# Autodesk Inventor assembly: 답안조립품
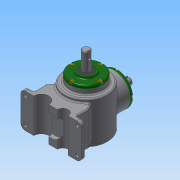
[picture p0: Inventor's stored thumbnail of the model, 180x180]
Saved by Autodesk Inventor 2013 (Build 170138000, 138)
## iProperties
Created: 2018-08
Part Number: 답안조립품
Document SubType Name: Assembly
Designer: user
Author: user
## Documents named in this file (14)
- C:\Users\user\Desktop\480808V1010\답안조립품.iam
- C:\Users\user\Desktop\480808V1010\답안조립품.ipt
- C:\Users\user\Desktop\480808V1010\메인 축.ipt
- 메인 축.ipt
- C:\Users\user\Desktop\480808V1010\메인 베벨기어.ipt
- C:\Users\user\Desktop\480808V1010\베어링 6203.ipt
- C:\Users\user\Desktop\480808V1010\키 5x5.ipt
- C:\Users\user\Desktop\480808V1010\커버.ipt
- C:\Users\user\Desktop\480808V1010\오일실 17 32 8.ipt
- C:\Users\user\Desktop\480808V1010\볼트 M4.ipt
- C:\Users\user\Desktop\480808V1010\서브 축.ipt
- 서브 축.ipt
- C:\Users\user\Desktop\480808V1010\키 4x4.ipt
- C:\Users\user\Desktop\480808V1010\서브 베벨기어.ipt
